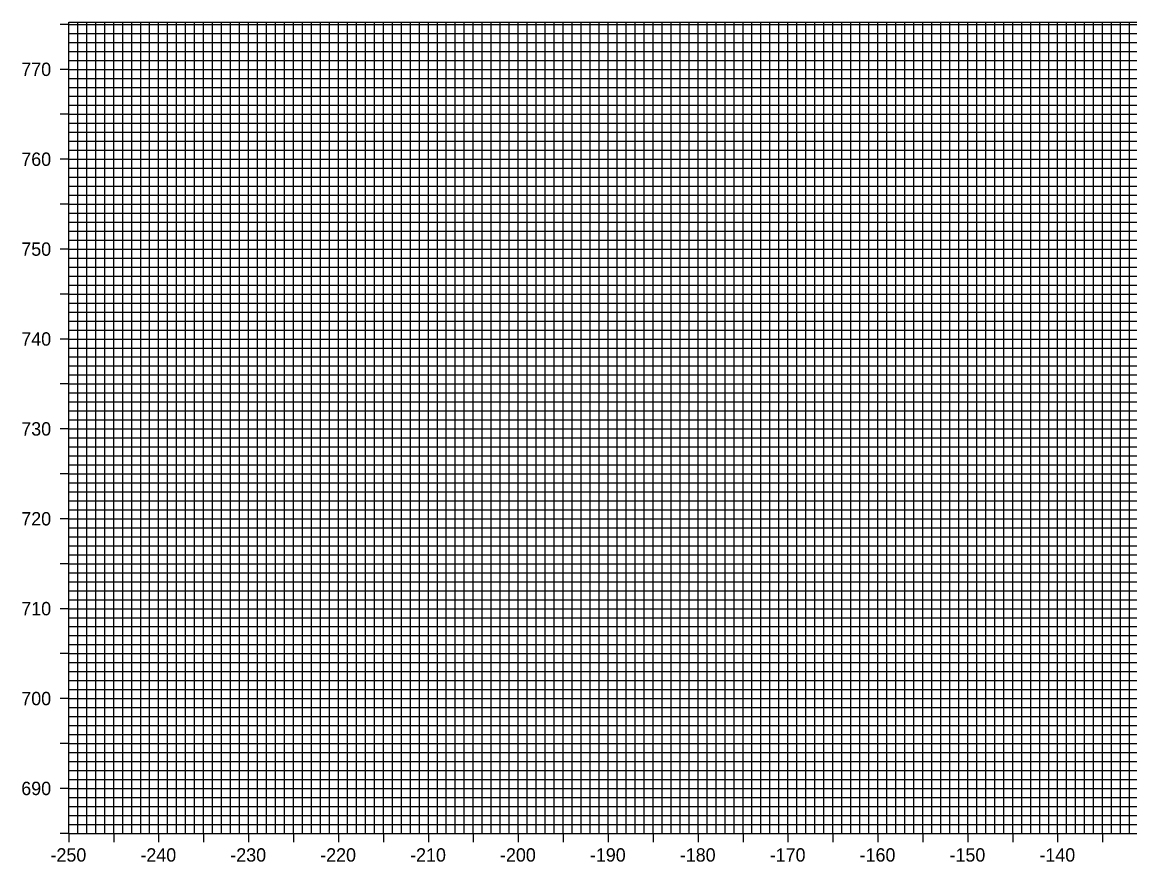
# Model space of a CAD drawing. Extents: x -255 to 55, y 682 to 775.
# Drawn here: x -255.2 to -132, y 681.8 to 775.3 of the extents above; entities that cross this region are included whole.
import ezdxf

# ---------------------------------------------------------------- set-up
doc = ezdxf.new("R2010")
doc.units = 0
for name, color, linetype in [('E_NCDOT_Vertical_Profile_Ground_Line', 7, 'Continuous'), ('P_HYD_Contour_Major', 7, 'Continuous'), ('P_HYD_Contour_Minor', 7, 'Continuous'), ('P_HYD_TC_Ditch_DDE', 7, 'Continuous'), ('P_HYD_TL_Slope_Stake_Fill', 7, 'Continuous')]:
    doc.layers.add(name, color=color, linetype=linetype)

msp = doc.modelspace()

# ---------------------------------------------------------------- linework, layer by layer
at = {"layer": 'P_HYD_Contour_Major'}
for p, q in [((-249, 685), (-249, 775.25)), ((-248, 685), (-248, 775.25)), ((-247, 685), (-247, 775.25)), ((-246, 685), (-246, 775.25)), ((-244, 685), (-244, 775.25)), ((-243, 685), (-243, 775.25)), ((-242, 685), (-242, 775.25)), ((-241, 685), (-241, 775.25)), ((-239, 685), (-239, 775.25)), ((-238, 685), (-238, 775.25)), ((-237, 685), (-237, 775.25)), ((-236, 685), (-236, 775.25)), ((-234, 685), (-234, 775.25)), ((-233, 685), (-233, 775.25)), ((-232, 685), (-232, 775.25)), ((-231, 685), (-231, 775.25)), ((-229, 685), (-229, 775.25)), ((-228, 685), (-228, 775.25)), ((-227, 685), (-227, 775.25)), ((-226, 685), (-226, 775.25)), ((-224, 685), (-224, 775.25)), ((-223, 685), (-223, 775.25)), ((-222, 685), (-222, 775.25)), ((-221, 685), (-221, 775.25)), ((-219, 685), (-219, 775.25)), ((-218, 685), (-218, 775.25)), ((-217, 685), (-217, 775.25)), ((-216, 685), (-216, 775.25)), ((-214, 685), (-214, 775.25)), ((-213, 685), (-213, 775.25)), ((-212, 685), (-212, 775.25)), ((-211, 685), (-211, 775.25)), ((-209, 685), (-209, 775.25)), ((-208, 685), (-208, 775.25)), ((-207, 685), (-207, 775.25)), ((-206, 685), (-206, 775.25)), ((-204, 685), (-204, 775.25)), ((-203, 685), (-203, 775.25)), ((-202, 685), (-202, 775.25)), ((-201, 685), (-201, 775.25)), ((-199, 685), (-199, 775.25)), ((-198, 685), (-198, 775.25)), ((-197, 685), (-197, 775.25)), ((-196, 685), (-196, 775.25)), ((-194, 685), (-194, 775.25)), ((-193, 685), (-193, 775.25)), ((-192, 685), (-192, 775.25)), ((-191, 685), (-191, 775.25)), ((-189, 685), (-189, 775.25)), ((-188, 685), (-188, 775.25)), ((-187, 685), (-187, 775.25)), ((-186, 685), (-186, 775.25)), ((-184, 685), (-184, 775.25)), ((-183, 685), (-183, 775.25)), ((-182, 685), (-182, 775.25)), ((-181, 685), (-181, 775.25)), ((-179, 685), (-179, 775.25)), ((-178, 685), (-178, 775.25)), ((-177, 685), (-177, 775.25)), ((-176, 685), (-176, 775.25)), ((-174, 685), (-174, 775.25)), ((-173, 685), (-173, 775.25)), ((-172, 685), (-172, 775.25)), ((-171, 685), (-171, 775.25)), ((-169, 685), (-169, 775.25)), ((-168, 685), (-168, 775.25)), ((-167, 685), (-167, 775.25)), ((-166, 685), (-166, 775.25)), ((-164, 685), (-164, 775.25)), ((-163, 685), (-163, 775.25)), ((-162, 685), (-162, 775.25)), ((-161, 685), (-161, 775.25)), ((-159, 685), (-159, 775.25)), ((-158, 685), (-158, 775.25)), ((-157, 685), (-157, 775.25)), ((-156, 685), (-156, 775.25)), ((-154, 685), (-154, 775.25)), ((-153, 685), (-153, 775.25)), ((-152, 685), (-152, 775.25)), ((-151, 685), (-151, 775.25)), ((-149, 685), (-149, 775.25)), ((-148, 685), (-148, 775.25)), ((-147, 685), (-147, 775.25)), ((-146, 685), (-146, 775.25)), ((-144, 685), (-144, 775.25)), ((-143, 685), (-143, 775.25)), ((-142, 685), (-142, 775.25)), ((-141, 685), (-141, 775.25)), ((-139, 685), (-139, 775.25)), ((-138, 685), (-138, 775.25)), ((-137, 685), (-137, 775.25)), ((-136, 685), (-136, 775.25)), ((-134, 685), (-134, 775.25)), ((-133, 685), (-133, 775.25)), ((-132, 685), (-132, 775.25)), ((-250, 774), (50, 774)), ((-250, 773), (50, 773)), ((-250, 772), (50, 772)), ((-250, 771), (50, 771)), ((-250, 769), (50, 769)), ((-250, 768), (50, 768)), ((-250, 767), (50, 767)), ((-250, 766), (50, 766)), ((-250, 764), (50, 764)), ((-250, 763), (50, 763)), ((-250, 762), (50, 762)), ((-250, 761), (50, 761)), ((-250, 759), (50, 759)), ((-250, 758), (50, 758)), ((-250, 757), (50, 757)), ((-250, 756), (50, 756)), ((-250, 754), (50, 754)), ((-250, 753), (50, 753)), ((-250, 752), (50, 752)), ((-250, 751), (50, 751)), ((-250, 749), (50, 749)), ((-250, 748), (50, 748)), ((-250, 747), (50, 747)), ((-250, 746), (50, 746)), ((-250, 744), (50, 744)), ((-250, 743), (50, 743)), ((-250, 742), (50, 742)), ((-250, 741), (50, 741)), ((-250, 739), (50, 739)), ((-250, 738), (50, 738)), ((-250, 737), (50, 737)), ((-250, 736), (50, 736)), ((-250, 734), (50, 734)), ((-250, 733), (50, 733)), ((-250, 732), (50, 732)), ((-250, 731), (50, 731)), ((-250, 729), (50, 729)), ((-250, 728), (50, 728)), ((-250, 727), (50, 727)), ((-250, 726), (50, 726)), ((-250, 724), (50, 724)), ((-250, 723), (50, 723)), ((-250, 722), (50, 722)), ((-250, 721), (50, 721)), ((-250, 719), (50, 719)), ((-250, 718), (50, 718)), ((-250, 717), (50, 717)), ((-250, 716), (50, 716)), ((-250, 714), (50, 714)), ((-250, 713), (50, 713)), ((-250, 712), (50, 712)), ((-250, 711), (50, 711)), ((-250, 709), (50, 709)), ((-250, 708), (50, 708)), ((-250, 707), (50, 707)), ((-250, 706), (50, 706)), ((-250, 704), (50, 704)), ((-250, 703), (50, 703)), ((-250, 702), (50, 702)), ((-250, 701), (50, 701)), ((-250, 699), (50, 699)), ((-250, 698), (50, 698)), ((-250, 697), (50, 697)), ((-250, 696), (50, 696)), ((-250, 694), (50, 694)), ((-250, 693), (50, 693)), ((-250, 692), (50, 692)), ((-250, 691), (50, 691)), ((-250, 689), (50, 689)), ((-250, 688), (50, 688)), ((-250, 687), (50, 687)), ((-250, 686), (50, 686))]:
    msp.add_line(p, q, dxfattribs=at)
at = {"layer": 'P_HYD_Contour_Minor'}
for p, q in [((-245, 685), (-245, 775.25)), ((-240, 685), (-240, 775.25)), ((-235, 685), (-235, 775.25)), ((-230, 685), (-230, 775.25)), ((-225, 685), (-225, 775.25)), ((-220, 685), (-220, 775.25)), ((-215, 685), (-215, 775.25)), ((-210, 685), (-210, 775.25)), ((-205, 685), (-205, 775.25)), ((-200, 685), (-200, 775.25)), ((-195, 685), (-195, 775.25)), ((-190, 685), (-190, 775.25)), ((-185, 685), (-185, 775.25)), ((-180, 685), (-180, 775.25)), ((-175, 685), (-175, 775.25)), ((-170, 685), (-170, 775.25)), ((-165, 685), (-165, 775.25)), ((-160, 685), (-160, 775.25)), ((-155, 685), (-155, 775.25)), ((-150, 685), (-150, 775.25)), ((-145, 685), (-145, 775.25)), ((-140, 685), (-140, 775.25)), ((-135, 685), (-135, 775.25)), ((-250, 775), (-250.96, 775)), ((-250, 775), (50, 775)), ((-250, 770), (-250.96, 770)), ((-250, 770), (50, 770)), ((-250, 765), (-250.96, 765)), ((-250, 765), (50, 765)), ((-250, 760), (-250.96, 760)), ((-250, 760), (50, 760)), ((-250, 755), (-250.96, 755)), ((-250, 755), (50, 755)), ((-250, 750), (-250.96, 750)), ((-250, 750), (50, 750)), ((-250, 745), (-250.96, 745)), ((-250, 745), (50, 745)), ((-250, 740), (-250.96, 740)), ((-250, 740), (50, 740)), ((-250, 735), (-250.96, 735)), ((-250, 735), (50, 735)), ((-250, 730), (-250.96, 730)), ((-250, 730), (50, 730)), ((-250, 725), (-250.96, 725)), ((-250, 725), (50, 725)), ((-250, 720), (-250.96, 720)), ((-250, 720), (50, 720)), ((-250, 715), (-250.96, 715)), ((-250, 715), (50, 715)), ((-250, 710), (-250.96, 710)), ((-250, 710), (50, 710)), ((-250, 705), (-250.96, 705)), ((-250, 705), (50, 705)), ((-250, 700), (-250.96, 700)), ((-250, 700), (50, 700)), ((-250, 695), (-250.96, 695)), ((-250, 695), (50, 695)), ((-250, 690), (-250.96, 690)), ((-250, 690), (50, 690)), ((-250, 685), (-250.96, 685)), ((-250, 685), (-250, 684.04)), ((-245, 685), (-245, 684.04)), ((-240, 685), (-240, 684.04)), ((-235, 685), (-235, 684.04)), ((-230, 685), (-230, 684.04)), ((-225, 685), (-225, 684.04)), ((-220, 685), (-220, 684.04)), ((-215, 685), (-215, 684.04)), ((-210, 685), (-210, 684.04)), ((-205, 685), (-205, 684.04)), ((-200, 685), (-200, 684.04)), ((-195, 685), (-195, 684.04)), ((-190, 685), (-190, 684.04)), ((-185, 685), (-185, 684.04)), ((-180, 685), (-180, 684.04)), ((-175, 685), (-175, 684.04)), ((-170, 685), (-170, 684.04)), ((-165, 685), (-165, 684.04)), ((-160, 685), (-160, 684.04)), ((-155, 685), (-155, 684.04)), ((-150, 685), (-150, 684.04)), ((-145, 685), (-145, 684.04)), ((-140, 685), (-140, 684.04)), ((-135, 685), (-135, 684.04))]:
    msp.add_line(p, q, dxfattribs=at)
at = {"layer": 'P_HYD_TC_Ditch_DDE'}
for p, q in [((-240, 685), (-240, 775.25)), ((-230, 685), (-230, 775.25)), ((-220, 685), (-220, 775.25)), ((-210, 685), (-210, 775.25)), ((-200, 685), (-200, 775.25)), ((-190, 685), (-190, 775.25)), ((-180, 685), (-180, 775.25)), ((-170, 685), (-170, 775.25)), ((-160, 685), (-160, 775.25)), ((-150, 685), (-150, 775.25)), ((-140, 685), (-140, 775.25)), ((-250, 770), (50, 770)), ((-250, 760), (50, 760)), ((-250, 750), (50, 750)), ((-250, 740), (50, 740)), ((-250, 730), (50, 730)), ((-250, 720), (50, 720)), ((-250, 710), (50, 710)), ((-250, 700), (50, 700)), ((-250, 690), (50, 690))]:
    msp.add_line(p, q, dxfattribs=at)
at = {"layer": 'P_HYD_TL_Slope_Stake_Fill'}
for p, q in [((-250, 775.25), (50, 775.25)), ((-250, 685), (-250, 775.25)), ((-250, 685), (50, 685))]:
    msp.add_line(p, q, dxfattribs=at)

# ---------------------------------------------------------------- texts
at = {"layer": 'E_NCDOT_Vertical_Profile_Ground_Line'}
for s, p in [('770', (-255.28, 769.26)), ('760', (-255.28, 759.26)), ('750', (-255.28, 749.26)), ('740', (-255.28, 739.26)), ('730', (-255.28, 729.26)), ('720', (-255.28, 719.26)), ('710', (-255.28, 709.26)), ('700', (-255.28, 699.26)), ('690', (-255.28, 689.26)), ('-250', (-252.03, 681.86)), ('-240', (-242.03, 681.86)), ('-230', (-232.03, 681.86)), ('-220', (-222.03, 681.86)), ('-210', (-212.03, 681.86)), ('-200', (-202.03, 681.86)), ('-190', (-192.03, 681.86)), ('-180', (-182.03, 681.86)), ('-170', (-172.03, 681.86)), ('-160', (-162.03, 681.86)), ('-150', (-152.03, 681.86)), ('-140', (-142.03, 681.86))]:
    msp.add_text(s, height=1.488, dxfattribs=at).set_placement(p)

doc.saveas('drawing.dxf')
